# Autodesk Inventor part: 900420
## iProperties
Created: 2007-12
Part Number: 900420
Document SubType Name: Modeling
Designer: DV
Density: 1.13 g/cm^3
Material: Nylon Composite (Nylon, molybdenum disulphide)
Description: WIRE MOUNTING TAB - 90 DEGREE
Mass: 0.710151 g
Surface Area: 11.7735 cm^2
Volume: 0.628452 cm^3
Component Category: Electrical
Author: DV
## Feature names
1. Revolution1
2. Fillet1
3. Extrusion2
4. Sweep1
5. Fillet5
6. Fillet6
7. Fillet7
8. Extrusion4
